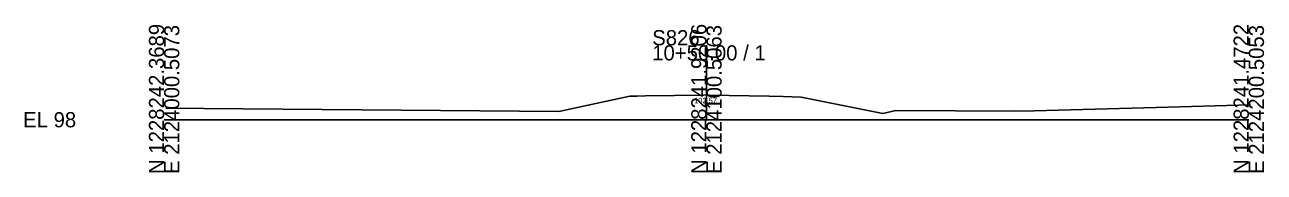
# Model space of a CAD drawing. Extents: x 2118382 to 2118616, y 1213030 to 1222057.
# Drawn here: x 2118381.9 to 2118610.4, y 1221030.1 to 1221057.3 of the extents above; entities that cross this region are included whole.
import ezdxf

# ---------------------------------------------------------------- set-up
doc = ezdxf.new("R2010")
doc.units = 0
for name, color, linetype in [('XS_CELL', 7, 'Continuous'), ('XS_X_GROUND', 7, 'Continuous'), ('XS_X_GROUND_TX', 7, 'Continuous')]:
    doc.layers.add(name, color=color, linetype=linetype)

msp = doc.modelspace()

# ---------------------------------------------------------------- linework, layer by layer
at = {"layer": 'XS_CELL'}
for p, q in [((2118507.6, 1221039.8), (2118507.6, 1221053.54)), ((2118407.6, 1221039.8), (2118507.6, 1221039.8)), ((2118507.6, 1221039.8), (2118607.6, 1221039.8))]:
    msp.add_line(p, q, dxfattribs=at)
at = {"layer": 'XS_X_GROUND'}
for p, q in [((2118482.64, 1221041.83), (2118493.5, 1221044.18)), ((2118493.5, 1221044.18), (2118494.74, 1221044.17)), ((2118494.74, 1221044.17), (2118496.39, 1221044.2)), ((2118496.39, 1221044.2), (2118507.07, 1221044.36)), ((2118507.07, 1221044.36), (2118507.6, 1221044.37)), ((2118507.6, 1221044.37), (2118508.07, 1221044.36)), ((2118508.07, 1221044.36), (2118519.19, 1221044.16)), ((2118519.19, 1221044.16), (2118521.76, 1221044.09)), ((2118521.76, 1221044.09), (2118525.05, 1221043.95)), ((2118525.05, 1221043.95), (2118536.14, 1221041.73)), ((2118407.91, 1221041.95), (2118414.9, 1221041.89)), ((2118414.9, 1221041.89), (2118480.4, 1221041.35)), ((2118480.4, 1221041.35), (2118482.64, 1221041.83)), ((2118536.14, 1221041.73), (2118540.12, 1221040.94)), ((2118540.12, 1221040.94), (2118542.5, 1221041.53)), ((2118542.5, 1221041.53), (2118564.44, 1221041.37)), ((2118564.44, 1221041.37), (2118568.03, 1221041.43)), ((2118568.03, 1221041.43), (2118590.55, 1221042.06)), ((2118590.55, 1221042.06), (2118607.91, 1221042.55))]:
    msp.add_line(p, q, dxfattribs=at)

# ---------------------------------------------------------------- texts
at = {"layer": 'XS_CELL'}
for s, p in [('N 1228242.3689', (2118407.6, 1221029.8)), ('E 2124000.5073', (2118410.4, 1221029.8)), ('N 1228241.9206', (2118507.6, 1221029.8)), ('E 2124100.5063', (2118510.4, 1221029.8)), ('N 1228241.4722', (2118607.6, 1221029.8)), ('E 2124200.5053', (2118610.4, 1221029.8))]:
    msp.add_text(s, height=2.8, rotation=90, dxfattribs=at).set_placement(p)
for s, p in [('S826', (2118497.6, 1221053.54)), ('10+50.00 / 1', (2118497.6, 1221050.74)), ('EL 98', (2118381.6, 1221038.4))]:
    msp.add_text(s, height=2.8, dxfattribs=at).set_placement(p)
at = {"layer": 'XS_X_GROUND_TX'}
msp.add_text('102.57', height=1, dxfattribs=at).set_placement((2118505.32, 1221042.85))

doc.saveas('drawing.dxf')
